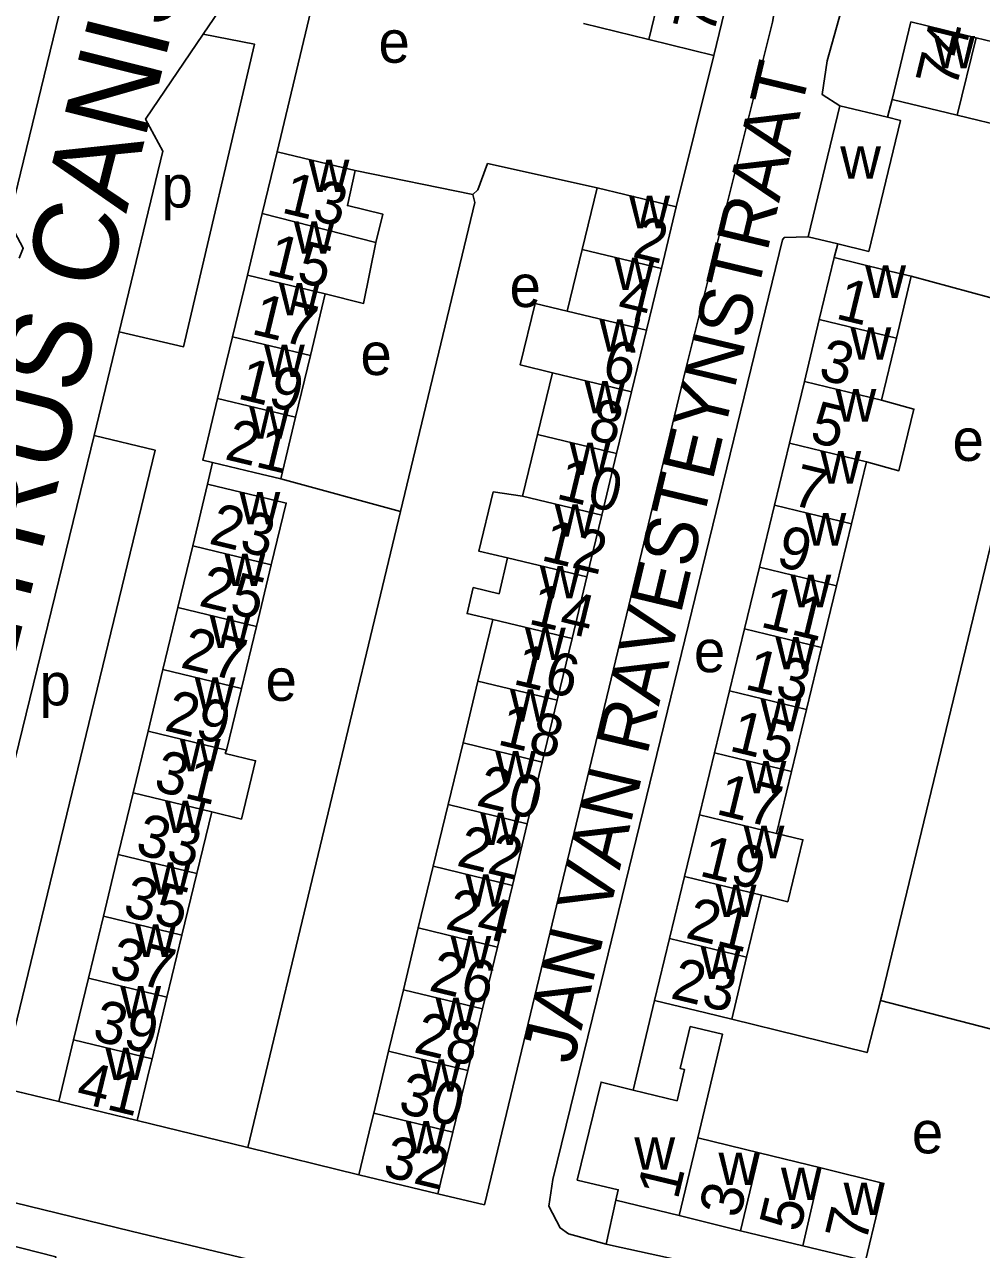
# Model space of a CAD drawing. Extents: x 162804 to 165059, y 381530 to 382901.
# Drawn here: x 163507.1 to 163597.8, y 382106.1 to 382222.2 of the extents above; entities that cross this region are included whole.
import ezdxf

# ---------------------------------------------------------------- set-up
doc = ezdxf.new("R2010")
doc.units = 0
for name, color, linetype in [('BLT_Basislijn', 7, 'Continuous'), ('BLT_Bebouwing', 7, 'Continuous'), ('BLT_Centroide', 7, 'Continuous'), ('BLT_Huisnummer', 7, 'Continuous'), ('BLT_Huisnummer_ tussenligend', 7, 'Continuous'), ('BLT_Onderverdeling_panden', 7, 'Continuous'), ('BLT_Straatnaam', 7, 'Continuous'), ('BLT_Straatnaam_hoofdweg', 7, 'Continuous')]:
    doc.layers.add(name, color=color, linetype=linetype)

msp = doc.modelspace()

# ---------------------------------------------------------------- linework, layer by layer
at = {"layer": 'BLT_Basislijn'}
for p, q in [((163531.04, 382210.12), (163535.41, 382228.34)), ((163568.88, 382204.9), (163572.44, 382219.26)), ((163588.92, 382213.39), (163589.35, 382215.07)), ((163549.59, 382206.07), (163538.43, 382208.34)), ((163583.87, 382200.1), (163584.2, 382201.39)), ((163591.17, 382198.33), (163604.02, 382194.84)), ((163516.06, 382193.05), (163513.68, 382183.24)), ((163513.68, 382183.24), (163512.39, 382177.93)), ((163524.45, 382178.63), (163524.92, 382180.69)), ((163531.38, 382179.13), (163542.75, 382176.05)), ((163512.39, 382177.93), (163502.98, 382139.65)), ((163542.75, 382176.05), (163528.25, 382115.77)), ((163566.83, 382129.71), (163564.8, 382121.22)), ((163601.42, 382126.29), (163588.25, 382129.72)), ((163504.82, 382121.46), (163510.33, 382120.13)), ((163528.25, 382115.77), (163517.77, 382118.33)), ((163538.78, 382113.2), (163528.25, 382115.77)), ((163562.25, 382106.63), (163563.15, 382110.8)), ((163553.62, 382099.14), (163517.21, 382107.85))]:
    msp.add_line(p, q, dxfattribs=at)
for points in [[(163516.72, 382240.56), (163516.01, 382237.47), (163513.45, 382235.81), (163505.61, 382203.55), (163506.97, 382200.99), (163506.59, 382200.05)], [(163577.49, 382231.23), (163579.06, 382228.61), (163578.02, 382222.4), (163569.76, 382189.42), (163550.69, 382110.35), (163546.29, 382111.38)], [(163584.4, 382214.48), (163582.73, 382215.55), (163583.19, 382218.74), (163585.18, 382225.87), (163587.83, 382228.45), (163591.81, 382228.37), (163634.14, 382217.78), (163636.14, 382216.71), (163637.58, 382214.99), (163638.26, 382212.97), (163638.03, 382210.78), (163636.11, 382202.48), (163635.95, 382202.25), (163631.41, 382202.47)], [(163526.2, 382226.34), (163525.5, 382223.45), (163524.03, 382221.28)], [(163524.03, 382221.28), (163518.57, 382213.2), (163520.22, 382210.19), (163516.06, 382193.05)], [(163524.03, 382221.28), (163528.89, 382220.32), (163522.18, 382191.65), (163516.06, 382193.05)], [(163549.59, 382206.07), (163550.08, 382206.53), (163551, 382209.01), (163561.38, 382206.71)], [(163549.59, 382206.07), (163549.79, 382205.32), (163542.75, 382176.05)], [(163562.25, 382106.63), (163558.68, 382107.58), (163557.89, 382108.15), (163556.81, 382110.23), (163557.17, 382112.73), (163561.75, 382131.42), (163578.97, 382201.79), (163579.13, 382202.01), (163581.4, 382202.07)], [(163604.02, 382194.84), (163588.41, 382130.31), (163588.25, 382129.72)], [(163513.68, 382183.24), (163519.47, 382181.85), (163504.82, 382121.46)], [(163588.25, 382129.72), (163586.97, 382124.77), (163574.14, 382127.94)], [(163506.09, 382110.56), (163505.23, 382106.64), (163510.06, 382105.43), (163502.37, 382074.08), (163499.06, 382065.94), (163492.43, 382050.42), (163488.21, 382052.07), (163486.32, 382046.81)], [(163517.21, 382107.85), (163506.09, 382110.56)], [(163595.63, 382099.32), (163562.66, 382106.52), (163562.25, 382106.63)]]:
    msp.add_lwpolyline(points, dxfattribs=at)
at = {"layer": 'BLT_Bebouwing'}
for p, q in [((163566.27, 382220.77), (163560.1, 382222.29)), ((163572.44, 382219.26), (163566.27, 382220.77)), ((163597.31, 382220.93), (163603.48, 382219.44)), ((163595.53, 382213.58), (163589.35, 382215.07)), ((163584.4, 382214.48), (163581.4, 382202.07)), ((163588.92, 382213.39), (163584.4, 382214.48)), ((163601.71, 382212.09), (163595.53, 382213.58)), ((163531.04, 382210.12), (163529.63, 382204.28)), ((163559.97, 382200.87), (163561.38, 382206.71)), ((163529.63, 382204.28), (163528.22, 382198.44)), ((163568.88, 382204.9), (163567.47, 382199.06)), ((163581.4, 382202.07), (163584.2, 382201.39)), ((163558.55, 382195.03), (163559.97, 382200.87)), ((163583.87, 382200.1), (163582.45, 382194.24)), ((163528.22, 382198.44), (163526.81, 382192.6)), ((163567.47, 382199.06), (163566.06, 382193.22)), ((163591.17, 382198.33), (163589.76, 382192.47)), ((163535.61, 382196.66), (163534.2, 382190.81)), ((163582.45, 382194.24), (163581.03, 382188.37)), ((163566.06, 382193.22), (163564.65, 382187.37)), ((163526.81, 382192.6), (163525.4, 382186.76)), ((163589.76, 382192.47), (163588.34, 382186.6)), ((163534.2, 382190.81), (163532.79, 382184.97)), ((163555.73, 382183.34), (163557.14, 382189.18)), ((163581.03, 382188.37), (163579.61, 382182.5)), ((163564.65, 382187.37), (163563.23, 382181.53)), ((163532.79, 382184.97), (163531.38, 382179.13)), ((163554.32, 382177.49), (163555.73, 382183.34)), ((163579.61, 382182.5), (163578.19, 382176.64)), ((163563.23, 382181.53), (163561.82, 382175.68)), ((163586.92, 382180.74), (163585.5, 382174.87)), ((163524.45, 382178.63), (163523.04, 382172.78)), ((163578.19, 382176.64), (163576.77, 382170.77)), ((163561.82, 382175.68), (163560.41, 382169.84)), ((163585.5, 382174.87), (163584.08, 382169)), ((163523.04, 382172.78), (163521.63, 382166.93)), ((163529.08, 382165.13), (163530.49, 382170.98)), ((163576.77, 382170.77), (163575.35, 382164.91)), ((163560.41, 382169.84), (163559, 382163.99)), ((163584.08, 382169), (163582.66, 382163.14)), ((163521.63, 382166.93), (163520.21, 382161.08)), ((163527.66, 382159.28), (163529.08, 382165.13)), ((163550.08, 382159.96), (163551.49, 382165.8)), ((163575.35, 382164.91), (163573.93, 382159.04)), ((163559, 382163.99), (163557.59, 382158.15)), ((163582.66, 382163.14), (163581.24, 382157.27)), ((163520.21, 382161.08), (163518.8, 382155.23)), ((163526.25, 382153.43), (163527.66, 382159.28)), ((163548.67, 382154.11), (163550.08, 382159.96)), ((163573.93, 382159.04), (163572.51, 382153.17)), ((163557.59, 382158.15), (163556.17, 382152.3)), ((163581.24, 382157.27), (163579.82, 382151.41)), ((163518.8, 382155.23), (163517.39, 382149.38)), ((163547.26, 382148.27), (163548.67, 382154.11)), ((163572.51, 382153.17), (163571.09, 382147.31)), ((163556.17, 382152.3), (163554.76, 382146.45)), ((163579.82, 382151.41), (163578.4, 382145.54)), ((163517.39, 382149.38), (163515.98, 382143.53)), ((163523.43, 382141.73), (163524.84, 382147.58)), ((163545.84, 382142.42), (163547.26, 382148.27)), ((163554.76, 382146.45), (163553.35, 382140.61)), ((163571.09, 382147.31), (163569.67, 382141.44)), ((163515.98, 382143.53), (163514.57, 382137.68)), ((163522.01, 382135.88), (163523.43, 382141.73)), ((163544.43, 382136.58), (163545.84, 382142.42)), ((163553.35, 382140.61), (163551.94, 382134.76)), ((163569.67, 382141.44), (163568.25, 382135.58)), ((163576.98, 382139.67), (163575.56, 382133.81)), ((163514.57, 382137.68), (163513.15, 382131.83)), ((163520.6, 382130.03), (163522.01, 382135.88)), ((163543.02, 382130.73), (163544.43, 382136.58)), ((163551.94, 382134.76), (163550.52, 382128.92)), ((163568.25, 382135.58), (163566.83, 382129.71)), ((163575.56, 382133.81), (163574.14, 382127.94)), ((163513.15, 382131.83), (163511.74, 382125.98)), ((163519.19, 382124.18), (163520.6, 382130.03)), ((163541.61, 382124.89), (163543.02, 382130.73)), ((163550.52, 382128.92), (163549.11, 382123.07)), ((163511.74, 382125.98), (163510.33, 382120.13)), ((163540.2, 382119.04), (163541.61, 382124.89)), ((163549.11, 382123.07), (163547.7, 382117.23)), ((163510.33, 382120.13), (163517.77, 382118.33)), ((163547.7, 382117.23), (163546.29, 382111.38)), ((163570.92, 382116.7), (163576.76, 382115.27)), ((163576.76, 382115.27), (163582.59, 382113.84)), ((163546.29, 382111.38), (163538.78, 382113.2)), ((163569.15, 382109.33), (163563.15, 382110.8)), ((163574.98, 382107.87), (163569.15, 382109.33)), ((163580.9, 382106.45), (163574.98, 382107.87))]:
    msp.add_line(p, q, dxfattribs=at)
for points in [[(163568.06, 382228.09), (163574.23, 382226.57), (163572.44, 382219.26)], [(163589.35, 382215.07), (163591.13, 382222.43), (163597.31, 382220.93)], [(163584.2, 382201.39), (163587.14, 382200.68), (163590.14, 382213.09), (163588.92, 382213.39)], [(163538.43, 382208.34), (163535.9, 382208.95), (163531.04, 382210.12)], [(163538.43, 382208.34), (163537.7, 382205.03), (163541.06, 382204.22), (163540.4, 382201.52)], [(163561.38, 382206.71), (163564.02, 382206.07), (163568.88, 382204.9)], [(163540.4, 382201.52), (163539.24, 382195.75), (163535.61, 382196.66)], [(163591.17, 382198.33), (163588.73, 382198.92), (163583.87, 382200.1)], [(163557.14, 382189.18), (163554.1, 382189.92), (163555.51, 382195.76), (163558.55, 382195.03)], [(163525.4, 382186.76), (163523.99, 382180.91), (163524.92, 382180.69)], [(163588.34, 382186.6), (163591.41, 382185.74), (163590, 382179.9), (163586.92, 382180.74)], [(163524.92, 382180.69), (163528.85, 382179.74), (163531.38, 382179.13)], [(163530.49, 382170.98), (163531.9, 382176.83), (163529.31, 382177.46), (163524.45, 382178.63)], [(163552.9, 382171.65), (163550.18, 382172.27), (163551.54, 382177.89), (163554.32, 382177.49)], [(163551.49, 382165.8), (163549.05, 382166.37), (163549.64, 382168.83), (163552.08, 382168.25), (163552.9, 382171.65)], [(163524.84, 382147.58), (163527.66, 382146.89), (163529, 382152.42), (163526.13, 382153.12), (163526.25, 382153.43)], [(163578.4, 382145.54), (163580.89, 382144.94), (163579.45, 382139.06), (163576.98, 382139.67)], [(163566.83, 382129.71), (163571.69, 382128.53), (163574.14, 382127.94)], [(163564.8, 382121.22), (163568.96, 382120.2), (163569.68, 382123.16), (163569.24, 382123.27), (163570.21, 382127.25)], [(163570.21, 382127.25), (163573.27, 382126.5), (163570.92, 382116.7)], [(163517.77, 382118.33), (163518.95, 382123.19), (163519.19, 382124.18)], [(163563.15, 382110.8), (163563.38, 382111.77), (163559.49, 382112.69), (163561.76, 382121.97), (163564.8, 382121.22)], [(163538.78, 382113.2), (163539.96, 382118.06), (163540.2, 382119.04)], [(163582.59, 382113.84), (163588.57, 382112.38), (163588, 382109.89), (163586.83, 382105.03), (163580.9, 382106.45)]]:
    msp.add_lwpolyline(points, dxfattribs=at)
at = {"layer": 'BLT_Onderverdeling_panden'}
for p, q in [((163566.27, 382220.77), (163568.06, 382228.09)), ((163595.53, 382213.58), (163597.31, 382220.93)), ((163540.4, 382201.52), (163529.63, 382204.28)), ((163567.47, 382199.06), (163559.97, 382200.87)), ((163535.61, 382196.66), (163528.22, 382198.44)), ((163566.06, 382193.22), (163558.55, 382195.03)), ((163589.76, 382192.47), (163582.45, 382194.24)), ((163534.2, 382190.81), (163526.81, 382192.6)), ((163564.65, 382187.37), (163557.14, 382189.18)), ((163588.34, 382186.6), (163581.03, 382188.37)), ((163532.79, 382184.97), (163525.4, 382186.76)), ((163563.23, 382181.53), (163555.73, 382183.34)), ((163586.92, 382180.74), (163579.61, 382182.5)), ((163561.82, 382175.68), (163554.32, 382177.49)), ((163585.5, 382174.87), (163578.19, 382176.64)), ((163523.04, 382172.78), (163530.49, 382170.98)), ((163560.41, 382169.84), (163552.9, 382171.65)), ((163584.08, 382169), (163576.77, 382170.77)), ((163521.63, 382166.93), (163529.08, 382165.13)), ((163559, 382163.99), (163551.49, 382165.8)), ((163582.66, 382163.14), (163575.35, 382164.91)), ((163520.21, 382161.08), (163527.66, 382159.28)), ((163557.59, 382158.15), (163550.08, 382159.96)), ((163581.24, 382157.27), (163573.93, 382159.04)), ((163518.8, 382155.23), (163526.25, 382153.43)), ((163556.17, 382152.3), (163548.67, 382154.11)), ((163579.82, 382151.41), (163572.51, 382153.17)), ((163517.39, 382149.38), (163524.84, 382147.58)), ((163554.76, 382146.45), (163547.26, 382148.27)), ((163578.4, 382145.54), (163571.09, 382147.31)), ((163515.98, 382143.53), (163523.43, 382141.73)), ((163553.35, 382140.61), (163545.84, 382142.42)), ((163576.98, 382139.67), (163569.67, 382141.44)), ((163514.57, 382137.68), (163522.01, 382135.88)), ((163551.94, 382134.76), (163544.43, 382136.58)), ((163575.56, 382133.81), (163568.25, 382135.58)), ((163513.15, 382131.83), (163520.6, 382130.03)), ((163550.52, 382128.92), (163543.02, 382130.73)), ((163511.74, 382125.98), (163519.19, 382124.18)), ((163549.11, 382123.07), (163541.61, 382124.89)), ((163547.7, 382117.23), (163540.2, 382119.04)), ((163569.15, 382109.33), (163570.92, 382116.7)), ((163574.98, 382107.87), (163576.76, 382115.27)), ((163580.9, 382106.45), (163582.59, 382113.84))]:
    msp.add_line(p, q, dxfattribs=at)

# ---------------------------------------------------------------- texts
at = {"layer": 'BLT_Centroide'}
for s, p in [('e', (163540.65, 382218.56)), ('w', (163593.33, 382218.02)), ('w', (163584.43, 382207.58)), ('w', (163534.03, 382206.31)), ('p', (163520.08, 382204.84)), ('w', (163564.42, 382202.88)), ('w', (163532.62, 382200.47)), ('w', (163563.02, 382197.03)), ('e', (163553.08, 382195.41)), ('w', (163586.8, 382196.28)), ('w', (163531.21, 382194.62)), ('w', (163561.6, 382191.19)), ('w', (163585.4, 382190.41)), ('w', (163529.8, 382188.78)), ('e', (163538.94, 382188.97)), ('w', (163560.19, 382185.34)), ('w', (163583.98, 382184.56)), ('w', (163528.39, 382182.94)), ('e', (163595.08, 382180.83)), ('w', (163558.77, 382179.5)), ('w', (163582.55, 382178.69)), ('w', (163527.47, 382174.81)), ('w', (163557.36, 382173.66)), ('w', (163581.13, 382172.81)), ('w', (163526.05, 382168.97)), ('w', (163555.95, 382167.81)), ('w', (163579.71, 382166.97)), ('w', (163524.65, 382163.09)), ('w', (163554.54, 382161.97)), ('e', (163570.56, 382160.81)), ('w', (163578.29, 382161.09)), ('p', (163508.51, 382157.67)), ('w', (163523.23, 382157.25)), ('e', (163529.94, 382158.1)), ('w', (163553.12, 382156.12)), ('w', (163576.87, 382155.22)), ('w', (163521.82, 382151.41)), ('w', (163551.72, 382150.28)), ('w', (163575.46, 382149.34)), ('w', (163520.41, 382145.56)), ('w', (163550.3, 382144.44)), ('w', (163575.27, 382143.19)), ('w', (163518.99, 382139.72)), ('w', (163548.89, 382138.59)), ('w', (163572.62, 382137.62)), ('w', (163517.59, 382133.84)), ('w', (163547.48, 382132.75)), ('w', (163571.2, 382131.75)), ('w', (163516.17, 382128)), ('w', (163546.06, 382126.91)), ('w', (163514.76, 382122.16)), ('w', (163544.66, 382121.06)), ('e', (163591.22, 382115.22)), ('w', (163543.24, 382115.22)), ('w', (163564.91, 382113.66)), ('w', (163572.89, 382112.22)), ('w', (163578.81, 382110.8)), ('w', (163584.75, 382109.38))]:
    msp.add_text(s, height=4, dxfattribs=at).set_placement(p)
at = {"layer": 'BLT_Huisnummer'}
for s, rotation, p in [('72', 76.2277, (163572.4, 382221.1)), ('74', 76.4156, (163595.42, 382216.01)), ('13', 346.4205, (163531.34, 382204.39)), ('2', 346.4174, (163564.61, 382200.2)), ('1', 346.3979, (163583.88, 382194.35)), ('17', 346.426, (163528.48, 382192.89)), ('6', 346.4174, (163561.69, 382188.54)), ('5', 346.3979, (163581.42, 382182.68)), ('21', 346.4223, (163525.96, 382181.02)), ('10', 346.4174, (163557.38, 382177.3)), ('9', 346.3961, (163578.23, 382170.92)), ('25', 346.4225, (163523.5, 382167.14)), ('14', 346.4191, (163554.75, 382165.43)), ('13', 346.3999, (163575.25, 382159.25)), ('29', 346.4225, (163520.24, 382155.32)), ('18', 346.4174, (163551.81, 382153.99)), ('17', 346.3981, (163572.53, 382147.4)), ('33', 346.4208, (163517.49, 382143.62)), ('22', 346.4174, (163547.94, 382142.51)), ('37', 346.4208, (163514.99, 382131.96)), ('26', 346.4174, (163545.32, 382130.68)), ('23', 346.3973, (163568.22, 382129.95)), ('41', 346.4281, (163511.84, 382120.13)), ('32', 346.4174, (163540.94, 382113.12)), ('1', 76.5055, (163569.02, 382110.74)), ('7', 76.5029, (163586.84, 382106.6))]:
    msp.add_text(s, height=4, rotation=rotation, dxfattribs=at).set_placement(p)
at = {"layer": 'BLT_Huisnummer_ tussenligend'}
for s, rotation, p in [('15', 346.4205, (163529.88, 382198.54)), ('4', 346.4174, (163563.14, 382194.62)), ('3', 346.3979, (163582.25, 382188.61)), ('19', 346.426, (163527.16, 382186.77)), ('8', 346.4174, (163560.37, 382182.96)), ('7', 346.3979, (163579.68, 382176.71)), ('23', 346.4223, (163524.46, 382173.02)), ('12', 346.4174, (163555.94, 382171.45)), ('11', 346.3961, (163576.74, 382165.14)), ('27', 346.4225, (163521.76, 382161.29)), ('16', 346.4191, (163553.29, 382159.72)), ('15', 346.3999, (163573.79, 382153.4)), ('31', 346.4225, (163519.22, 382149.63)), ('20', 346.4174, (163549.8, 382148.22)), ('19', 346.3981, (163570.95, 382141.55)), ('35', 346.4208, (163516.3, 382137.77)), ('24', 346.4174, (163546.87, 382136.53)), ('21', 346.3981, (163569.65, 382135.67)), ('39', 346.4208, (163513.4, 382125.98)), ('28', 346.4174, (163543.87, 382124.83)), ('30', 346.4174, (163542.4, 382119.12)), ('3', 76.5055, (163574.88, 382108.97)), ('5', 76.5055, (163580.59, 382107.64))]:
    msp.add_text(s, height=4, rotation=rotation, dxfattribs=at).set_placement(p)
at = {"layer": 'BLT_Straatnaam'}
msp.add_text('JAN VAN RAVESTEYNSTRAAT', height=5, rotation=76.5617, dxfattribs=at).set_placement((163559.11, 382123.56))
at = {"layer": 'BLT_Straatnaam_hoofdweg'}
msp.add_text('ST PETRUS CANISIUSLAAN', height=8, rotation=75.8593, dxfattribs=at).set_placement((163499.45, 382135.62))

doc.saveas('drawing.dxf')
